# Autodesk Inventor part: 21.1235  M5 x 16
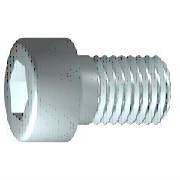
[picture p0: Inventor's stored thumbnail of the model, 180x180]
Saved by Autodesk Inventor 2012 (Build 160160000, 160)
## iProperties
Created: 2006-02
Part Number: 21.1235  M5 x 16
Material: Steel, Mild
Description: Cylinder Head Cap Screw
Document SubType Name: Modeling
Standard: DIN 7984
Designer: Andy Moles
Standards Organization: DIN
Language: en-US
Size Designation: M5 x 16
Categories: <MemberInstance><Categories><Category DisplayName="Fasteners" InternalName="e4da775c-781d-43d5-af7c-5136215cf5a6" Mnemonic="FSTN"><Category DisplayName="Bolts"
Density: 7.86 g/cm^3
Mass: 3.81606 g
Surface Area: 4.77789 cm^2
Volume: 0.485504 cm^3
Author: Andy Moles
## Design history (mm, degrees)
workplane "Work Plane1"
revolve "Body" stored, may be unused: angle "d10" = 90 deg
sketch "Sketch2"
  geometry: L1 (0, -5.1)-(0, 6.8) reference; L2 (-5.1, 0)-(6.8, 0) reference; L3 (1.732, 0)-(0.866, -1.5); L4 (0.866, -1.5)-(-0.866, -1.5); L5 (-0.866, -1.5)-(-1.732, 0); L6 (-1.732, 0)-(-0.866, 1.5); L7 (-0.866, 1.5)-(0.866, 1.5); L8 (0.866, 1.5)-(1.732, 0); 2 further points
  constraints: 12 end point, 1 coincident, 1 horizontal alignment, 1 point on line, 12 other
extrude "Slot" join sketch "Sketch2" stored distance "d11" = 10; taper "d12" = 0 deg
body "Solid1"
fillet "Fillet1" dims "d17" = 0.5 (= RR)
feature "Thread" dims "d13" = 16, "d14" = 0
chamfer "Chamfer1" distance "d15" = 0.49076 (= -0.5 x SPD + 0.5 x GD); stored, may be unused: second distance "d16" = 0.49076 (= GUL), angle "d27" = 45 deg
sketch "Sketch1"
  geometry: L1 (0.2, 0)-(16, 0); L2 (16, 0)-(16, 2.5); L3 (16, 2.5)-(2.4, 2.5); L4 (2.4, 2.5)-(1.909, 2.5); L5 (1.909, 2.5)-(0, 2.5); L6 (0, 2.5)-(0, 4.25); L7 (0, 4.25)-(-3.5, 4.25); L8 (-3.5, 4.25)-(-3.5, 1.732); L9 (-3.5, 1.732)-(-0.8, 1.732); L10 (-0.8, 1.732)-(0.2, 0); L11 (-5.45, 0)-(21.85, 0) reference; L12 (0, -0.425)-(0, 5.525) reference; L13 (2.4, 2.5)-(0, 2.5)
  constraints: 22 end point, 6 parallel, 2 collinear, 2 perpendicular, 1 horizontal, 1 point on line
  dimensions: "d1" = 13.6 distance from line of L3.end L2 (= GEL); "d2" = 0.49086 distance of L4.end L3.end (computed from GAL); "d3" = 3.5 distance between parallel lines of L8 L6 (= KOH); "d4" = 2.7 distance of L8.end L9.end (= INTI); "d5" = 60 deg angle of L10 L1; "d6" = 5 diameter of L3 L1 (= GD); "d7" = 5 diameter of L5 L1 (= BDM); "d8" = 3.4641 diameter of L9 L1 (= 1.1547 x SW); "d9" = 8.5 diameter of L7 L1 (= KOD); "d26" = 16 distance between parallel lines of L12 L2 (= NLG)
other parameters: "GD" = 5 (= NND) [user parameter; used in 2 equation terms], "NLG" = 16 [user parameter; used in 1 equation term], "GEL" = 13.6 [user parameter; used in 1 equation term], "KOD" = 8.5 [user parameter; used in 1 equation term], "KOH" = 3.5 [user parameter; used in 1 equation term], "INTI" = 2.7 [user parameter; used in 1 equation term], "GAL" = 0.49076 (= 0.61345 x PTC) [user parameter; used in 1 equation term], "GUL" = 0.49076 (= 0.61345 x PTC) [user parameter; used in 1 equation term], "BDM" = 5 (= NND) [user parameter; used in 1 equation term], "SW" = 3 [user parameter; used in 2 equation terms], "RR" = 0.5 [user parameter; used in 1 equation term], "SPD" = 4.01848 (= NND - 1.2269 x PTC) [user parameter; used in 1 equation term], "d19" = 0, "d28" = 0, "d29" = 0, "TOA" = 30 deg [user parameter], "GD1" = 4.01848 (= THREADDIA - 1.2269 x PTC) [user parameter], "THREADDIA" = 5 [user parameter; used in 1 equation term], "FAWI" = 45 deg [user parameter], "ANG" = 120 deg [user parameter], "TPU" = 12.5 (computed from PTC) [user parameter], "PTC" = 0.8 [user parameter; used in 5 equation terms], "NND" = 5 [user parameter; used in 3 equation terms], "E0" = 3.465 (= 1.155 x SW) [user parameter]
